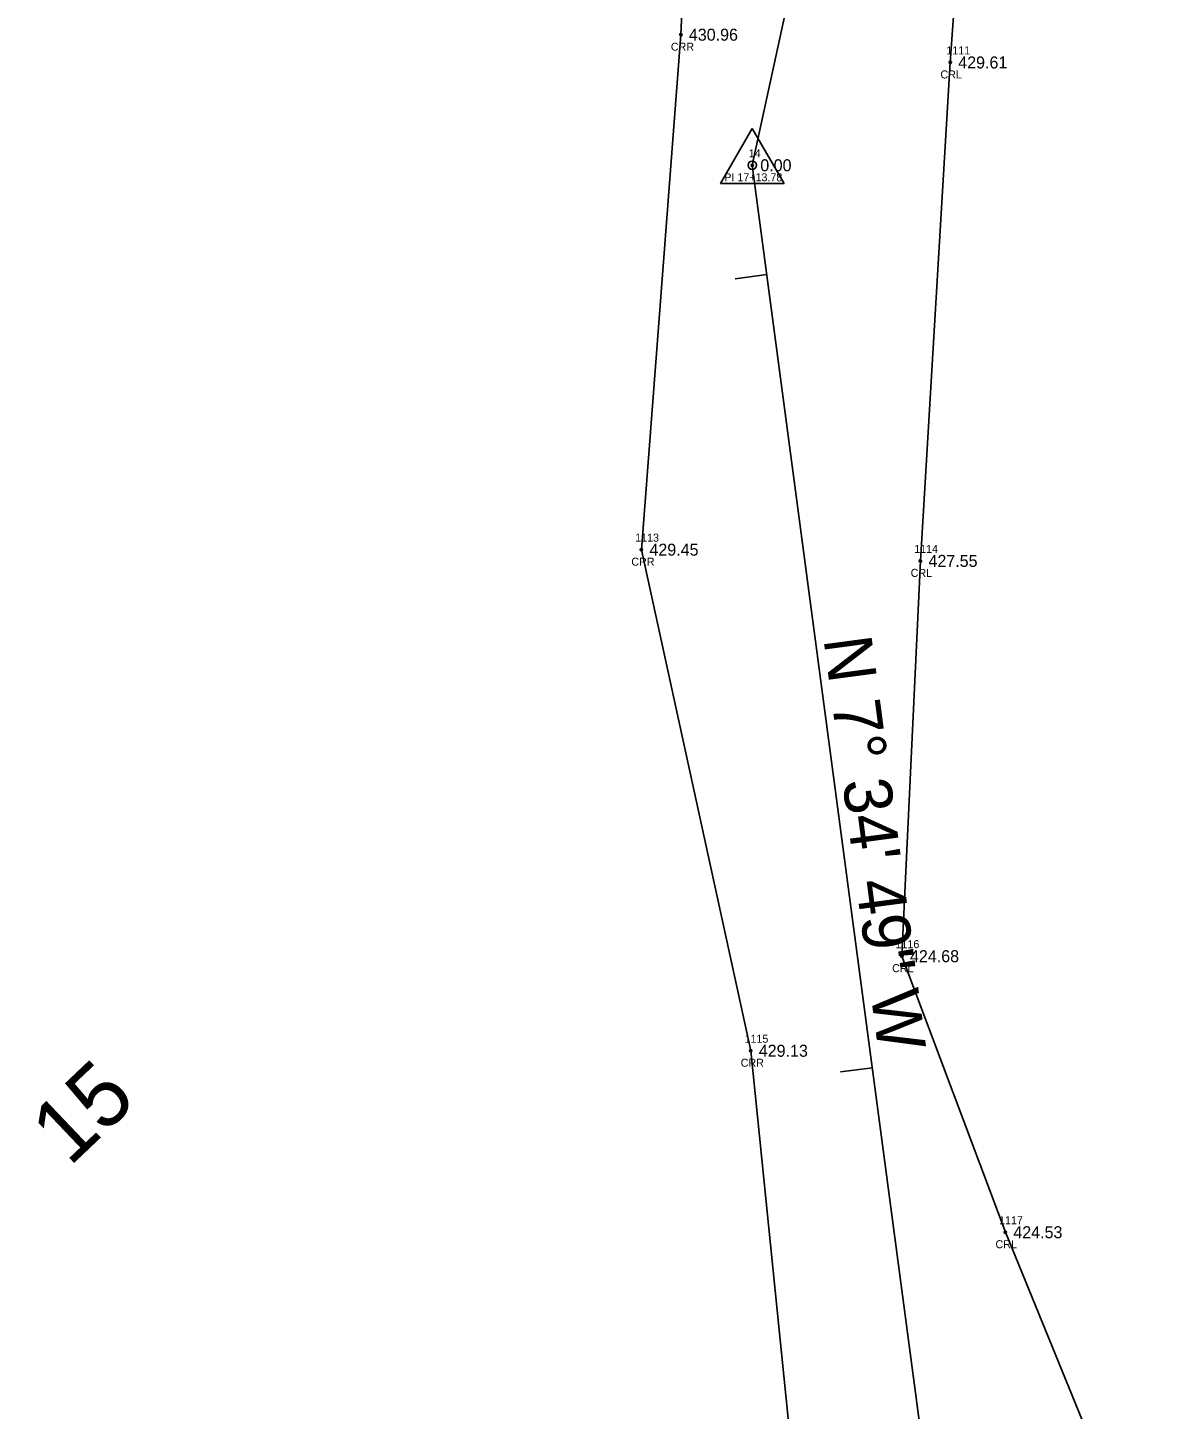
# Model space of a CAD drawing. Extents: x 1858454 to 1858924, y 1147053 to 1148170.
# Drawn here: x 1858751.6 to 1858894.9, y 1147803.4 to 1147976.1 of the extents above; entities that cross this region are included whole.
import ezdxf

# ---------------------------------------------------------------- set-up
doc = ezdxf.new("R2010")
doc.units = 0
for name, color, linetype in [('RD_EX_H2O', 7, 'Continuous'), ('RD_EX_H2O_txCode', 7, 'Continuous'), ('RD_EX_TX_H2O_ELEV', 7, 'Continuous'), ('RD_HC_Cl', 7, 'Continuous'), ('RD_HC_Data', 7, 'Continuous'), ('RD_HC_Data_Tic', 7, 'Continuous'), ('RD_HC_Survey_ELEV', 7, 'Continuous'), ('RD_HC_TX_Sta50', 7, 'Continuous'), ('RD_HC_txCode', 7, 'Continuous'), ('RD_SMD_Locator', 7, 'Continuous')]:
    doc.layers.add(name, color=color, linetype=linetype)

msp = doc.modelspace()

# ---------------------------------------------------------------- linework, layer by layer
at = {"layer": 'RD_EX_H2O'}
for points in [[(1858883.69, 1148147.48), (1858852.78, 1148112.64), (1858836.04, 1148037.73), (1858833.26, 1147975.2), (1858828.33, 1147910.84), (1858842, 1147848.22), (1858847.52, 1147794.04)], [(1858879.83, 1148102.54), (1858871.42, 1148034.27), (1858866.93, 1147971.73), (1858863.21, 1147909.44), (1858860.9, 1147860.04), (1858873.82, 1147825.54), (1858891.79, 1147781.55), (1858894.95, 1147773.07), (1858887.01, 1147735.25), (1858825.08, 1147733.03), (1858791.14, 1147702.41), (1858765.02, 1147654.77), (1858740.99, 1147628.76), (1858706.35, 1147596.83), (1858671.87, 1147580.02), (1858637.61, 1147560.56), (1858613.46, 1147539.88), (1858609.2, 1147499), (1858608.26, 1147474.71), (1858583.43, 1147442.99), (1858542.68, 1147417.32), (1858497.34, 1147430.55)]]:
    msp.add_lwpolyline(points, dxfattribs=at)
at = {"layer": 'RD_HC_Cl'}
for p, q in [((1858842.19, 1147958.88), (1858876.7, 1148118.07)), ((1858865, 1147787.44), (1858842.19, 1147958.88))]:
    msp.add_line(p, q, dxfattribs=at)
at = {"layer": 'RD_HC_Data'}
for p, q in [((1858838.22, 1147956.59), (1858842.19, 1147963.47)), ((1858842.19, 1147963.47), (1858846.16, 1147956.59)), ((1858838.22, 1147956.59), (1858846.16, 1147956.59))]:
    msp.add_line(p, q, dxfattribs=at)
msp.add_circle((1858842.19, 1147958.88), 0.529, dxfattribs=at)
at = {"layer": 'RD_HC_Data_Tic'}
for p, q in [((1858844.01, 1147945.23), (1858840.04, 1147944.7)), ((1858857.2, 1147846.1), (1858853.23, 1147845.58))]:
    msp.add_line(p, q, dxfattribs=at)
at = {"layer": 'RD_SMD_Locator'}
for centre in [(1858833.26, 1147975.2), (1858866.93, 1147971.73), (1858842.19, 1147958.88), (1858828.33, 1147910.84), (1858863.21, 1147909.44), (1858860.9, 1147860.04), (1858842, 1147848.22), (1858873.82, 1147825.54)]:
    msp.add_circle(centre, 0.15, dxfattribs=at)

# ---------------------------------------------------------------- texts
at = {"layer": 'RD_EX_H2O_txCode'}
for s, p in [('CRR', (1858832.01, 1147973.2)), ('1111', (1858866.44, 1147972.73)), ('CRL', (1858865.71, 1147969.73)), ('1113', (1858827.55, 1147911.84)), ('1114', (1858862.43, 1147910.44)), ('CRR', (1858827.07, 1147908.84)), ('CRL', (1858861.98, 1147907.44)), ('1116', (1858860.09, 1147861.04)), ('CRL', (1858859.67, 1147858.04)), ('1115', (1858841.22, 1147849.22)), ('CRR', (1858840.74, 1147846.22)), ('1117', (1858873.04, 1147826.54)), ('CRL', (1858872.59, 1147823.54))]:
    msp.add_text(s, height=1, dxfattribs=at).set_placement(p)
at = {"layer": 'RD_EX_TX_H2O_ELEV'}
for s, p in [('430.96', (1858834.26, 1147974.45)), ('429.61', (1858867.93, 1147970.98)), ('429.45', (1858829.33, 1147910.09)), ('427.55', (1858864.21, 1147908.69)), ('424.68', (1858861.9, 1147859.29)), ('429.13', (1858843, 1147847.47)), ('424.53', (1858874.82, 1147824.79))]:
    msp.add_text(s, height=1.5, dxfattribs=at).set_placement(p)
at = {"layer": 'RD_HC_Data'}
msp.add_text('N 7%%d 34\' 49" W', height=6, rotation=277.5803, dxfattribs=at).set_placement((1858851.08, 1147899.68))
at = {"layer": 'RD_HC_Survey_ELEV'}
msp.add_text('0.00', height=1.5, dxfattribs=at).set_placement((1858843.19, 1147958.13))
at = {"layer": 'RD_HC_TX_Sta50'}
msp.add_text('15', height=8, rotation=43.5432, dxfattribs=at).set_placement((1858756.83, 1147833.64))
at = {"layer": 'RD_HC_txCode'}
for s, p in [('14', (1858841.74, 1147959.88)), ('PI 17+13.78', (1858838.69, 1147956.88))]:
    msp.add_text(s, height=1, dxfattribs=at).set_placement(p)

doc.saveas('drawing.dxf')
